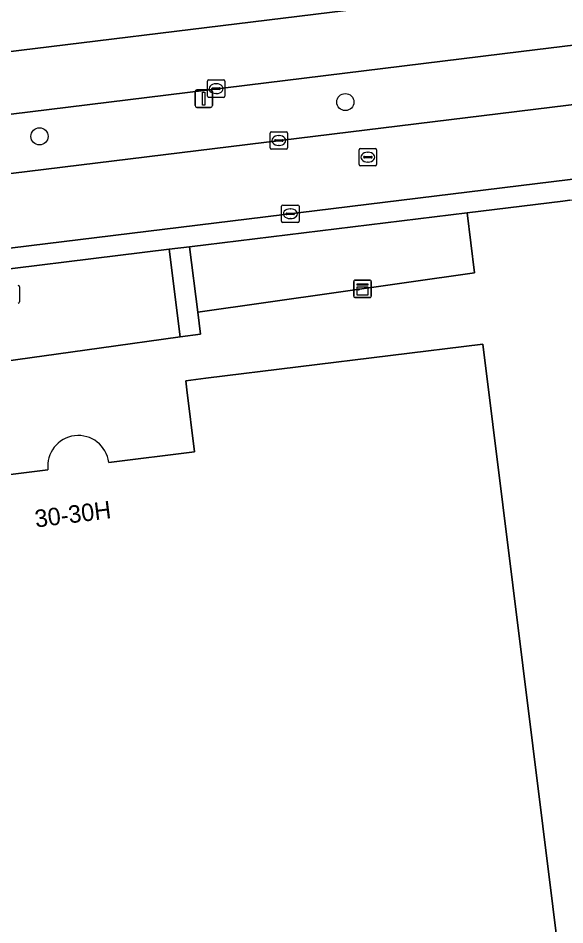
# Model space of a CAD drawing. Extents: x 161477 to 163040, y 383680 to 384871.
# Drawn here: x 162278.7 to 162310, y 384020 to 384072 of the extents above; entities that cross this region are included whole.
import ezdxf

# ---------------------------------------------------------------- set-up
doc = ezdxf.new("R2010")
doc.units = 0
for name, color, linetype in [('IMGEO_Berm_groen', 7, 'Continuous'), ('IMGEO_Boom', 7, 'Continuous'), ('IMGEO_Brandkraan', 7, 'Continuous'), ('IMGEO_Erf', 7, 'Continuous'), ('IMGEO_Groenvoorziening', 7, 'Continuous'), ('IMGEO_Kast', 7, 'Continuous'), ('IMGEO_Kolk', 7, 'Continuous'), ('IMGEO_Lichtmast', 7, 'Continuous'), ('IMGEO_Pand', 7, 'Continuous'), ('IMGEO_Pand_nummerreeks', 7, 'Continuous'), ('IMGEO_Rijbaan_lokaal_gesloten', 7, 'Continuous'), ('IMGEO_Rioolput', 7, 'Continuous'), ('IMGEO_Voetpad_open', 7, 'Continuous')]:
    doc.layers.add(name, color=color, linetype=linetype)

msp = doc.modelspace()

# ---------------------------------------------------------------- linework, layer by layer
at = {"layer": 'IMGEO_Berm_groen'}
for points in [[(162534.962, 384097.975), (162500, 384093.468), (162481.264, 384091.095), (162457.811, 384088.372), (162442.901, 384086.436), (162402.758, 384081.663), (162381.895, 384078.899), (162368.059, 384077.415), (162337.394, 384073.713), (162307.499, 384070.04), (162248.941, 384062.845), (162201.441, 384057.009), (162179.625, 384054.308), (162139.298, 384049.588), (162134.982, 384048.963), (162131.051, 384048.617), (162073.42, 384041.498), (162051.67, 384038.989), (162036.516, 384037.016), (162009.54, 384033.893)], [(162260.044, 384060.826), (162395.867, 384077.5), (162517.624, 384092.325)]]:
    msp.add_lwpolyline(points, dxfattribs=at)
at = {"layer": 'IMGEO_Boom'}
for centre in [(162297.434, 384067.152), (162279.927, 384065.187)]:
    msp.add_circle(centre, 0.489, dxfattribs=at)
at = {"layer": 'IMGEO_Brandkraan'}
msp.add_line((162278.777, 384056.57), (162278.777, 384055.718), dxfattribs=at)
msp.add_lwpolyline([(162278.777, 384056.57), (162278.777, 384055.718)], dxfattribs=at)
for centre, start, end in [((162278.701, 384056.568), 1.552, 88.448), ((162278.701, 384056.568), 1.552, 88.448), ((162278.701, 384055.72), 271.552, 358.448), ((162278.701, 384055.72), 271.552, 358.448)]:
    msp.add_arc(centre, 0.0765, start, end, dxfattribs=at)
at = {"layer": 'IMGEO_Erf'}
for points in [[(162310.294, 384061.528), (162309.894, 384061.479), (162304.416, 384060.808), (162304.825, 384057.373), (162288.985, 384055.124), (162289.141, 384053.868), (162287.977, 384053.705), (162283.349, 384053.058), (162274.705, 384051.849), (162255.631, 384049.181), (162256.037, 384045.334), (162253.15, 384045.041), (162246.984, 384044.273), (162242.158, 384043.659), (162242.26, 384042.603), (162242.123, 384042.572), (162242.201, 384041.92), (162242.368, 384040.506), (162240.302, 384040.262), (162240.134, 384041.676), (162214.99, 384038.711)], [(162283.887, 384046.518), (162288.8, 384047.122), (162288.363, 384050.675), (162288.299, 384051.191), (162289.441, 384051.332), (162305.312, 384053.285), (162309.876, 384016.491), (162292.783, 384014.407), (162292.526, 384016.511), (162262.151, 384012.807), (162258.158, 384045.553)], [(162258.158, 384045.553), (162257.926, 384047.454), (162275.006, 384049.556), (162275.07, 384049.04), (162275.507, 384045.487), (162280.41, 384046.09)]]:
    msp.add_lwpolyline(points, dxfattribs=at)
msp.add_arc((162282.149, 384046.303), 1.752, 7.0357, 186.9993, dxfattribs=at)
at = {"layer": 'IMGEO_Groenvoorziening'}
for points in [[(162288.522, 384058.862), (162288.985, 384055.124), (162304.825, 384057.373), (162304.416, 384060.808)], [(162287.358, 384058.72), (162287.977, 384053.705), (162289.141, 384053.868), (162288.985, 384055.124), (162288.522, 384058.862)]]:
    msp.add_lwpolyline(points, close=True, dxfattribs=at)
at = {"layer": 'IMGEO_Kast'}
for p, q in [((162297.918, 384056.034), (162297.918, 384056.875)), ((162297.918, 384056.875), (162297.918, 384056.034)), ((162297.993, 384056.959), (162298.834, 384056.959)), ((162298.834, 384056.959), (162297.993, 384056.959)), ((162298.918, 384056.884), (162298.918, 384056.043)), ((162298.918, 384056.043), (162298.918, 384056.884)), ((162298.843, 384055.959), (162298.002, 384055.959)), ((162298.002, 384055.959), (162298.843, 384055.959))]:
    msp.add_line(p, q, dxfattribs=at)
for points in [[(162298.113, 384056.749), (162298.713, 384056.749), (162298.713, 384056.664), (162298.113, 384056.664), (162298.113, 384056.749)], [(162298.113, 384056.574), (162298.713, 384056.574), (162298.713, 384056.085), (162298.113, 384056.085), (162298.113, 384056.574)]]:
    msp.add_lwpolyline(points, dxfattribs=at)
msp.add_circle((162298.197, 384056.423), 0.0377, dxfattribs=at)
for centre, start, end in [((162297.996, 384056.881), 92.4484, 184.2845), ((162297.996, 384056.881), 92.4484, 184.2845), ((162298.84, 384056.881), 2.4484, 94.2845), ((162298.84, 384056.881), 2.4484, 94.2845), ((162297.996, 384056.037), 182.4484, 274.2845), ((162297.996, 384056.037), 182.4484, 274.2845), ((162298.84, 384056.037), 272.4484, 4.2845), ((162298.84, 384056.037), 272.4484, 4.2845)]:
    msp.add_arc(centre, 0.0779, start, end, dxfattribs=at)
at = {"layer": 'IMGEO_Kolk'}
for p, q in [((162289.535, 384067.495), (162289.535, 384068.347)), ((162289.61, 384068.421), (162290.462, 384068.421)), ((162290.536, 384068.347), (162290.536, 384067.495)), ((162289.794, 384067.915), (162289.794, 384067.927)), ((162290.232, 384067.878), (162289.834, 384067.878)), ((162289.837, 384067.964), (162290.235, 384067.964)), ((162290.023, 384068.201), (162290.048, 384068.201)), ((162290.278, 384067.927), (162290.278, 384067.915)), ((162290.462, 384067.421), (162289.61, 384067.421)), ((162290.046, 384067.641), (162290.021, 384067.641)), ((162293.128, 384064.523), (162293.128, 384065.375)), ((162293.203, 384065.449), (162294.055, 384065.449)), ((162293.616, 384065.229), (162293.641, 384065.229)), ((162294.129, 384065.375), (162294.129, 384064.523)), ((162293.387, 384064.943), (162293.387, 384064.955)), ((162293.825, 384064.906), (162293.427, 384064.906)), ((162293.43, 384064.992), (162293.828, 384064.992)), ((162293.639, 384064.669), (162293.614, 384064.669)), ((162293.871, 384064.955), (162293.871, 384064.943)), ((162294.055, 384064.449), (162293.203, 384064.449)), ((162293.785, 384060.329), (162293.785, 384061.181)), ((162293.86, 384061.255), (162294.712, 384061.255)), ((162294.273, 384061.035), (162294.298, 384061.035)), ((162294.786, 384061.181), (162294.786, 384060.329)), ((162294.044, 384060.749), (162294.044, 384060.761)), ((162294.482, 384060.712), (162294.084, 384060.712)), ((162294.087, 384060.798), (162294.485, 384060.798)), ((162294.528, 384060.761), (162294.528, 384060.749)), ((162294.712, 384060.255), (162293.86, 384060.255)), ((162294.296, 384060.475), (162294.271, 384060.475))]:
    msp.add_line(p, q, dxfattribs=at)
for points in [[(162289.535, 384067.495), (162289.535, 384068.347)], [(162289.61, 384068.421), (162290.462, 384068.421)], [(162290.536, 384068.347), (162290.536, 384067.495)], [(162290.462, 384067.421), (162289.61, 384067.421)], [(162293.128, 384064.523), (162293.128, 384065.375)], [(162293.203, 384065.449), (162294.055, 384065.449)], [(162294.129, 384065.375), (162294.129, 384064.523)], [(162294.055, 384064.449), (162293.203, 384064.449)], [(162293.785, 384060.329), (162293.785, 384061.181)], [(162293.86, 384061.255), (162294.712, 384061.255)], [(162294.786, 384061.181), (162294.786, 384060.329)], [(162294.712, 384060.255), (162293.86, 384060.255)]]:
    msp.add_lwpolyline(points, dxfattribs=at)
for centre, radius, start, end in [((162289.612, 384068.345), 0.0765, 91.552, 178.448), ((162289.612, 384068.345), 0.0765, 91.552, 178.448), ((162290.46, 384068.345), 0.0765, 1.552, 88.448), ((162290.46, 384068.345), 0.0765, 1.552, 88.448), ((162289.834, 384067.924), 0.0403, 85.8775, 175.7526), ((162289.831, 384067.914), 0.0366, 178.938, 274.7102), ((162290.235, 384067.921), 0.043, 264.8664, 352.4533), ((162290.239, 384067.926), 0.0386, 1.7309, 96.639), ((162289.612, 384067.497), 0.0765, 181.552, 268.448), ((162289.612, 384067.497), 0.0765, 181.552, 268.448), ((162290.46, 384067.497), 0.0765, 271.552, 358.448), ((162290.46, 384067.497), 0.0765, 271.552, 358.448), ((162293.205, 384065.373), 0.0765, 91.552, 178.448), ((162293.205, 384065.373), 0.0765, 91.552, 178.448), ((162294.053, 384065.373), 0.0765, 1.552, 88.448), ((162294.053, 384065.373), 0.0765, 1.552, 88.448), ((162293.427, 384064.952), 0.0403, 85.8775, 175.7526), ((162293.424, 384064.942), 0.0366, 178.938, 274.7102), ((162293.828, 384064.949), 0.043, 264.8664, 352.4533), ((162293.832, 384064.954), 0.0386, 1.7309, 96.639), ((162293.205, 384064.525), 0.0765, 181.552, 268.448), ((162293.205, 384064.525), 0.0765, 181.552, 268.448), ((162294.053, 384064.525), 0.0765, 271.552, 358.448), ((162294.053, 384064.525), 0.0765, 271.552, 358.448), ((162293.862, 384061.179), 0.0765, 91.552, 178.448), ((162293.862, 384061.179), 0.0765, 91.552, 178.448), ((162294.71, 384061.179), 0.0765, 1.552, 88.448), ((162294.71, 384061.179), 0.0765, 1.552, 88.448), ((162294.084, 384060.758), 0.0403, 85.8775, 175.7526), ((162294.081, 384060.748), 0.0366, 178.938, 274.7102), ((162294.485, 384060.755), 0.043, 264.8664, 352.4533), ((162294.489, 384060.76), 0.0386, 1.7309, 96.639), ((162293.862, 384060.331), 0.0765, 181.552, 268.448), ((162293.862, 384060.331), 0.0765, 181.552, 268.448), ((162294.71, 384060.331), 0.0765, 271.552, 358.448), ((162294.71, 384060.331), 0.0765, 271.552, 358.448)]:
    msp.add_arc(centre, radius, start, end, dxfattribs=at)
for centre, major_axis, ratio, start_param, end_param in [((162290.022, 384067.921), (-0.387, 0.002), 0.722429, 4.712389, 7.853982), ((162290.047, 384067.921), (-0.39, 0.002), 0.717154, 1.570796, 4.712389), ((162293.615, 384064.949), (-0.387, 0.002), 0.722429, 4.712389, 7.853982), ((162293.64, 384064.949), (-0.39, 0.002), 0.717154, 1.570796, 4.712389), ((162294.272, 384060.755), (-0.387, 0.002), 0.722429, 4.712389, 7.853982), ((162294.297, 384060.755), (-0.39, 0.002), 0.717154, 1.570796, 4.712389)]:
    msp.add_ellipse(centre, major_axis=major_axis, ratio=ratio, start_param=start_param, end_param=end_param, dxfattribs=at)
at = {"layer": 'IMGEO_Lichtmast'}
for p, q in [((162288.93, 384067.848), (162289.72, 384067.848)), ((162289.72, 384067.848), (162288.93, 384067.848)), ((162288.83, 384066.948), (162288.83, 384067.748)), ((162288.83, 384067.748), (162288.83, 384066.948)), ((162289.82, 384067.748), (162289.82, 384066.948)), ((162289.82, 384066.948), (162289.82, 384067.748)), ((162289.72, 384066.848), (162288.93, 384066.848)), ((162288.93, 384066.848), (162289.72, 384066.848))]:
    msp.add_line(p, q, dxfattribs=at)
msp.add_lwpolyline([(162289.25, 384067.723), (162289.4, 384067.723), (162289.4, 384066.973), (162289.25, 384066.973), (162289.25, 384067.723)], dxfattribs=at)
for centre, start, end in [((162288.93, 384067.748), 90, 180), ((162288.93, 384067.748), 90, 180), ((162289.72, 384067.748), 0, 90), ((162289.72, 384067.748), 360, 90), ((162288.93, 384066.948), 180, 270), ((162288.93, 384066.948), 180, 270), ((162289.72, 384066.948), 270, 0), ((162289.72, 384066.948), 270, 0)]:
    msp.add_arc(centre, 0.1, start, end, dxfattribs=at)
at = {"layer": 'IMGEO_Pand'}
msp.add_lwpolyline([(162280.41, 384046.09), (162275.507, 384045.487), (162275.07, 384049.04), (162275.006, 384049.556), (162257.926, 384047.454), (162258.158, 384045.553), (162262.151, 384012.807), (162292.526, 384016.511), (162292.783, 384014.407), (162309.876, 384016.491), (162305.312, 384053.285), (162289.441, 384051.332), (162288.299, 384051.191), (162288.363, 384050.675), (162288.8, 384047.122), (162283.887, 384046.518)], dxfattribs=at)
msp.add_arc((162282.149, 384046.303), 1.752, 7.0357, 186.9993, dxfattribs=at)
at = {"layer": 'IMGEO_Rijbaan_lokaal_gesloten'}
msp.add_lwpolyline([(162523.472, 384100.182), (162541.672, 384102.783), (162554.672, 384105.134), (162566.872, 384107.635), (162574.422, 384109.336), (162609.421, 384117.982), (162609.604, 384121.678), (162602.378, 384119.861), (162582.678, 384114.817), (162570.302, 384112.064), (162562.353, 384110.296), (162552.451, 384108.269), (162542.23, 384106.474), (162518.729, 384102.971), (162500, 384100.675), (162391.371, 384087.519), (162295.197, 384075.687), (162278.569, 384073.661), (162247.846, 384069.907), (162248.391, 384066.39), (162263.747, 384068.271), (162307.132, 384073.594), (162328.972, 384076.274), (162436.622, 384089.378)], close=True, dxfattribs=at)
for points in [[(162523.472, 384100.182), (162436.622, 384089.378), (162328.972, 384076.274), (162307.132, 384073.594), (162263.747, 384068.271), (162248.391, 384066.39), (162248.941, 384062.845), (162307.499, 384070.04), (162337.394, 384073.713), (162368.059, 384077.415), (162381.895, 384078.899), (162402.758, 384081.663), (162442.901, 384086.436), (162457.811, 384088.372), (162481.264, 384091.095), (162500, 384093.468), (162534.962, 384097.975)], [(162517.624, 384092.325), (162395.867, 384077.5), (162260.044, 384060.826)], [(162261.855, 384056.776), (162395.494, 384073.171), (162405.589, 384074.388), (162472.495, 384082.536)]]:
    msp.add_lwpolyline(points, dxfattribs=at)
at = {"layer": 'IMGEO_Rioolput'}
for p, q in [((162298.223, 384063.57), (162298.223, 384064.422)), ((162298.298, 384064.496), (162299.15, 384064.496)), ((162298.711, 384064.276), (162298.736, 384064.276)), ((162299.224, 384064.422), (162299.224, 384063.57)), ((162298.482, 384063.99), (162298.482, 384064.002)), ((162298.92, 384063.953), (162298.522, 384063.953)), ((162298.525, 384064.039), (162298.923, 384064.039)), ((162298.734, 384063.716), (162298.709, 384063.716)), ((162298.966, 384064.002), (162298.966, 384063.99)), ((162299.15, 384063.496), (162298.298, 384063.496))]:
    msp.add_line(p, q, dxfattribs=at)
for points in [[(162298.223, 384063.57), (162298.223, 384064.422)], [(162298.298, 384064.496), (162299.15, 384064.496)], [(162299.224, 384064.422), (162299.224, 384063.57)], [(162299.15, 384063.496), (162298.298, 384063.496)]]:
    msp.add_lwpolyline(points, dxfattribs=at)
for centre, radius, start, end in [((162298.3, 384064.42), 0.0765, 91.552, 178.448), ((162298.3, 384064.42), 0.0765, 91.552, 178.448), ((162299.148, 384064.42), 0.0765, 1.552, 88.448), ((162299.148, 384064.42), 0.0765, 1.552, 88.448), ((162298.522, 384063.999), 0.0403, 85.8775, 175.7526), ((162298.519, 384063.989), 0.0366, 178.938, 274.7102), ((162298.923, 384063.996), 0.043, 264.8664, 352.4533), ((162298.927, 384064.001), 0.0386, 1.7309, 96.639), ((162298.3, 384063.572), 0.0765, 181.552, 268.448), ((162298.3, 384063.572), 0.0765, 181.552, 268.448), ((162299.148, 384063.572), 0.0765, 271.552, 358.448), ((162299.148, 384063.572), 0.0765, 271.552, 358.448)]:
    msp.add_arc(centre, radius, start, end, dxfattribs=at)
for centre, major_axis, ratio, start_param, end_param in [((162298.71, 384063.996), (-0.387, 0.002), 0.722429, 4.712389, 7.853982), ((162298.735, 384063.996), (-0.39, 0.002), 0.717154, 1.570796, 4.712389)]:
    msp.add_ellipse(centre, major_axis=major_axis, ratio=ratio, start_param=start_param, end_param=end_param, dxfattribs=at)
at = {"layer": 'IMGEO_Voetpad_open'}
for points in [[(162392.205, 384071.555), (162395.649, 384071.966), (162395.868, 384071.977), (162404.186, 384073.024), (162404.569, 384073.071), (162405.715, 384073.213), (162472.321, 384081.307), (162472.615, 384081.343), (162472.495, 384082.536), (162405.589, 384074.388), (162395.494, 384073.171), (162261.855, 384056.776)], [(162260.411, 384055.33), (162263.356, 384055.782), (162272.804, 384056.938), (162274.037, 384057.089), (162287.358, 384058.72), (162288.522, 384058.862), (162304.416, 384060.808), (162309.894, 384061.479), (162310.294, 384061.528), (162354.651, 384066.958), (162360.797, 384067.71), (162392.205, 384071.555)]]:
    msp.add_lwpolyline(points, dxfattribs=at)
msp.add_lwpolyline([(162274.037, 384057.089), (162274.549, 384053.074), (162274.705, 384051.849), (162283.349, 384053.058), (162287.977, 384053.705), (162287.358, 384058.72)], close=True, dxfattribs=at)

# ---------------------------------------------------------------- texts
at = {"layer": 'IMGEO_Pand_nummerreeks'}
msp.add_text('30-30H', height=1, rotation=7.1271, dxfattribs=at).set_placement((162279.72, 384042.784))

doc.saveas('drawing.dxf')
